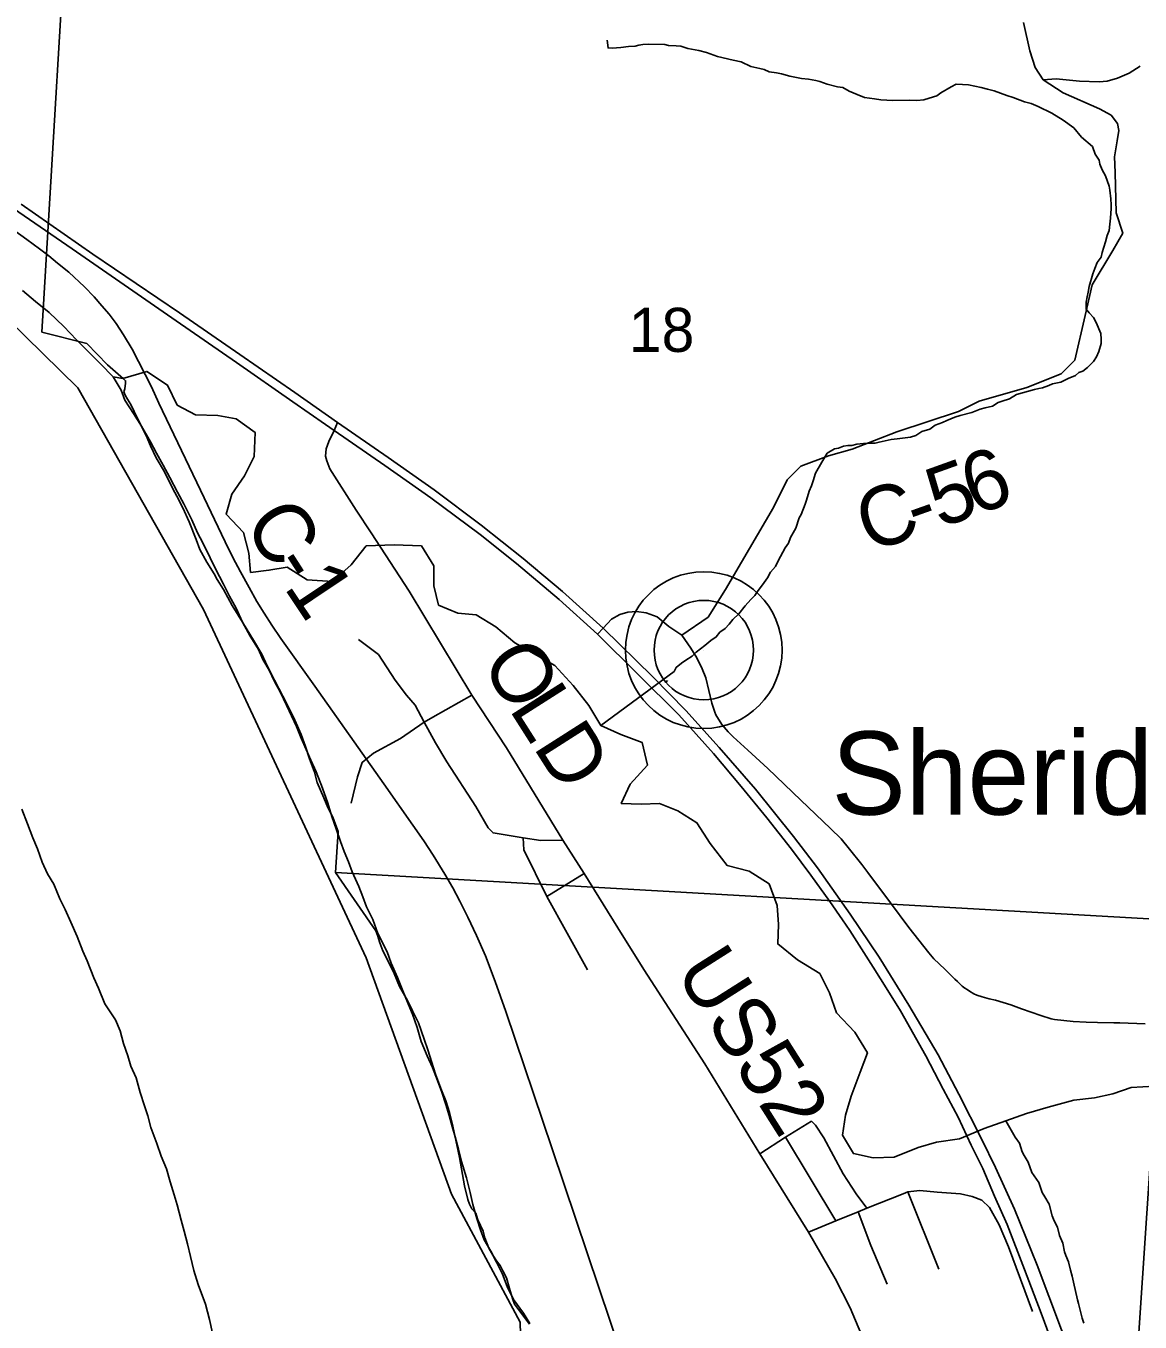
# Model space of a CAD drawing. Extents: x 0 to 45.4, y -2.2 to 22.
# Drawn here: x 2.837 to 3.896, y 17.917 to 19.147 of the extents above; entities that cross this region are included whole.
import ezdxf

# ---------------------------------------------------------------- set-up
doc = ezdxf.new("R2010")
doc.units = 0
for name, color, linetype in [('GM_X_Corporation', 7, 'Continuous'), ('GM_X_County_Road', 7, 'Continuous'), ('GM_X_County_Road_Text', 7, 'Continuous'), ('GM_X_Major_River', 7, 'Continuous'), ('GM_X_Minor_River', 7, 'Continuous'), ('GM_X_Rail_Line', 7, 'Continuous'), ('GM_X_Section_Text', 7, 'Continuous'), ('GM_X_Township_Road', 7, 'Continuous'), ('GM_X_Unincorporated', 7, 'Continuous'), ('GM_X_Unincorporated_Location', 7, 'Continuous'), ('GM_X_Unincorporated_Text', 7, 'Continuous'), ('GM_X_US_Route', 7, 'Continuous')]:
    doc.layers.add(name, color=color, linetype=linetype)

msp = doc.modelspace()

# ---------------------------------------------------------------- linework, layer by layer
at = {"layer": 'GM_X_Corporation'}
for points in [[(3.9206, 18.2985), (3.1315, 18.3434), (3.1341, 18.3824), (3.1315, 18.3892), (3.1288, 18.3961), (3.1243, 18.4052), (3.1205, 18.4143), (3.1141, 18.429), (3.1114, 18.4389), (3.1069, 18.4514), (3.1031, 18.4631), (3.099, 18.4745), (3.0929, 18.4882), (3.0857, 18.5029), (3.0736, 18.5261), (3.0649, 18.5431), (3.0615, 18.5507), (3.0536, 18.5639), (3.043, 18.581), (3.0335, 18.5969), (3.0252, 18.6121), (3.0191, 18.6216), (3.0161, 18.6269), (3.0093, 18.6382), (3.0025, 18.65), (2.9991, 18.6595), (2.9926, 18.6765), (2.9866, 18.6898), (2.9809, 18.7008), (2.9771, 18.7076), (2.9692, 18.7239), (2.9612, 18.7372), (2.9559, 18.7485), (2.9518, 18.7584), (2.9438, 18.7739), (2.937, 18.7879), (2.934, 18.7929), (2.9317, 18.7967), (2.9306, 18.7997), (2.9313, 18.8027), (2.9321, 18.808), (2.9321, 18.8103), (2.9302, 18.8122), (2.9151, 18.8255), (2.8954, 18.8456), (2.8526, 18.8566), (2.8813, 19.3385)], [(2.4503, 19.1527), (2.5862, 19.0536), (2.6706, 19.0104), (2.7255, 18.9508), (2.8035, 18.8848), (2.8867, 18.8036), (3.006, 18.5933), (3.1607, 18.2624), (3.2417, 18.0381), (3.3068, 17.9167), (3.3076, 17.8928), (3.2906, 17.8503), (3.2853, 17.7584), (3.3008, 17.64), (3.3557, 17.2765), (3.3572, 17.2298), (3.3712, 17.1086)], [(2.4503, 19.1527), (2.5862, 19.0536), (2.6706, 19.0104), (2.7255, 18.9508), (2.8035, 18.8848), (2.8867, 18.8036), (3.006, 18.5933), (3.1607, 18.2624), (3.2417, 18.0381), (3.3068, 17.9167), (3.3076, 17.8928), (3.2906, 17.8503), (3.2853, 17.7584), (3.3008, 17.64), (3.3557, 17.2765), (3.3572, 17.2298), (3.3712, 17.1086)], [(3.3157, 17.9148), (3.3104, 17.922), (3.3051, 17.9288), (3.3013, 17.9337), (3.2994, 17.939), (3.2968, 17.9485), (3.2937, 17.9587), (3.2903, 17.9655), (3.2877, 17.9705), (3.2843, 17.975), (3.2809, 17.9803), (3.2771, 17.9868), (3.2733, 17.9966), (3.2718, 18.0031), (3.2665, 18.0137), (3.2646, 18.0201), (3.2608, 18.0243), (3.2586, 18.0288), (3.257, 18.033), (3.254, 18.0459), (3.2521, 18.0569), (3.2491, 18.0728), (3.2457, 18.0895), (3.2423, 18.1054), (3.2397, 18.1156), (3.2363, 18.1266), (3.2321, 18.1368), (3.2264, 18.152), (3.2192, 18.1751), (3.2158, 18.1853), (3.2102, 18.2009), (3.2045, 18.2123), (3.1999, 18.2221), (3.1924, 18.2354), (3.1871, 18.2475), (3.1814, 18.2593), (3.1765, 18.2691), (3.1735, 18.2767), (3.1712, 18.2839), (3.1697, 18.2881), (3.1315, 18.3434), (3.9206, 18.2985), (3.854, 17.3067)]]:
    msp.add_lwpolyline(points, dxfattribs=at)
msp.add_lwpolyline([(3.9206, 18.2985), (5.0121, 18.2353), (4.9524, 17.2347), (3.854, 17.3067)], close=True, dxfattribs=at)
at = {"layer": 'GM_X_County_Road'}
for points in [[(3.4602, 18.5689), (3.4852, 18.5858), (3.5019, 18.6121), (3.5474, 18.6901), (3.5604, 18.7162), (3.5734, 18.7292), (3.5995, 18.7389), (3.6222, 18.7454), (3.6645, 18.7617), (3.7231, 18.7812), (3.7426, 18.7909), (3.7881, 18.8039), (3.8207, 18.8169), (3.8337, 18.8299), (3.8434, 18.8722), (3.8499, 18.9015), (3.8695, 18.934), (3.8792, 18.9503), (3.8727, 18.9698), (3.8718, 19.0081), (3.8711, 19.0228), (3.8737, 19.0382), (3.8752, 19.048), (3.874, 19.0546), (3.868, 19.0624), (3.857, 19.0684), (3.8224, 19.0835), (3.8036, 19.0961), (3.796, 19.1077), (3.7907, 19.1234), (3.7847, 19.1505)], [(3.1333, 18.7707), (3.1302, 18.763), (3.125, 18.7526), (3.1225, 18.7457), (3.122, 18.7386), (3.1233, 18.7342), (3.1262, 18.7268), (3.1512, 18.6874), (3.1652, 18.6661)], [(3.1652, 18.6661), (3.2013, 18.6106), (3.261, 18.5117), (3.2937, 18.4617), (3.3474, 18.3741), (3.3677, 18.3426), (3.3996, 18.2909), (3.4243, 18.2515), (3.4822, 18.1618), (3.5344, 18.0765), (3.5806, 18.002), (3.606, 17.9581), (3.6201, 17.9303), (3.6499, 17.8596)], [(3.3803, 18.5697), (3.3857, 18.5755), (3.3936, 18.5841), (3.4014, 18.5885), (3.409, 18.5907), (3.4173, 18.5914), (3.4266, 18.5899), (3.4369, 18.5863), (3.448, 18.5769), (3.4602, 18.5689), (3.4688, 18.5566), (3.4745, 18.5473), (3.4796, 18.5367), (3.483, 18.5284), (3.4888, 18.5044), (3.4916, 18.4956), (3.4926, 18.4931), (3.4983, 18.4841), (3.4987, 18.4836), (3.5042, 18.4769), (3.5091, 18.4722), (3.523, 18.4596), (3.542, 18.4421), (3.5735, 18.4121), (3.6016, 18.3853), (3.6115, 18.3754), (3.6197, 18.3655), (3.6312, 18.3511), (3.6371, 18.3436), (3.6584, 18.3146), (3.6759, 18.2913), (3.6949, 18.2672), (3.6997, 18.2617), (3.71, 18.2517), (3.7189, 18.2429), (3.7197, 18.2422), (3.722, 18.2399), (3.7267, 18.2357), (3.7291, 18.2337), (3.7314, 18.2323), (3.7335, 18.2309), (3.7375, 18.2284), (3.7406, 18.2271), (3.7457, 18.2254), (3.7521, 18.2237), (3.7583, 18.2222), (3.7729, 18.2179), (3.7829, 18.2142), (3.8013, 18.2079), (3.8112, 18.2047), (3.8142, 18.2041), (3.8232, 18.2029), (3.8319, 18.202), (3.8444, 18.2014), (3.8552, 18.2012), (3.8707, 18.2007), (3.8764, 18.2008), (3.9002, 18.1998)]]:
    msp.add_lwpolyline(points, dxfattribs=at)
at = {"layer": 'GM_X_Major_River'}
for points in [[(3.1438, 18.3535), (3.1396, 18.3633), (3.1362, 18.3728), (3.132, 18.3849), (3.1279, 18.3967), (3.1241, 18.4092), (3.1192, 18.4236), (3.1132, 18.4392), (3.1082, 18.4502), (3.1037, 18.4604), (3.0988, 18.4711), (3.0943, 18.4821), (3.0897, 18.4923), (3.0848, 18.5025), (3.0788, 18.5151), (3.0735, 18.5249), (3.0686, 18.5355), (3.0625, 18.5458), (3.0584, 18.5553), (3.0504, 18.5678), (3.0432, 18.5811), (3.0372, 18.5943), (3.0308, 18.6057), (3.0251, 18.6171), (3.0175, 18.6319), (3.0123, 18.6421), (3.0054, 18.6566), (3.0005, 18.666), (2.9949, 18.6782), (2.9873, 18.6934), (2.9813, 18.7047), (2.9741, 18.7184), (2.9677, 18.7302), (2.9616, 18.7415), (2.9559, 18.7522), (2.9472, 18.7673), (2.9397, 18.7791), (2.9314, 18.792), (2.928, 18.8015), (2.9204, 18.814), (2.9083, 18.8265), (2.8955, 18.839), (2.8856, 18.8493), (2.8735, 18.8618), (2.8595, 18.8751), (2.8467, 18.8857), (2.8342, 18.8959)], [(2.8337, 18.4036), (2.839, 18.3896), (2.8439, 18.3763), (2.8484, 18.3661), (2.853, 18.3532), (2.8579, 18.3422), (2.8639, 18.3323), (2.8696, 18.3186), (2.8749, 18.3084), (2.8802, 18.2963), (2.8862, 18.2826), (2.8915, 18.2689), (2.8957, 18.2595), (2.9021, 18.2435), (2.9063, 18.2337), (2.9123, 18.2189), (2.9225, 18.2037), (2.927, 18.1931), (2.9301, 18.1813), (2.9342, 18.1696), (2.9372, 18.1597), (2.9422, 18.1487), (2.9459, 18.1346), (2.9501, 18.1221), (2.9531, 18.1126), (2.9561, 18.1013), (2.9618, 18.0861), (2.966, 18.0743), (2.9709, 18.0622), (2.9746, 18.05), (2.9784, 18.0375), (2.9811, 18.028), (2.9849, 18.0136), (2.9879, 18.003), (2.9909, 17.9909), (2.9939, 17.9791), (2.9969, 17.9658)], [(3.3161, 17.9153), (3.31, 17.9251), (3.3006, 17.938), (3.2945, 17.9506), (3.29, 17.9623), (3.2843, 17.9737), (3.279, 17.9839), (3.2726, 17.9949), (3.2692, 18.0044), (3.2658, 18.0151), (3.262, 18.0283), (3.2594, 18.0397), (3.256, 18.0538), (3.2511, 18.0693), (3.2484, 18.0807), (3.245, 18.0925), (3.2424, 18.1023), (3.2394, 18.1129), (3.2363, 18.1232), (3.2326, 18.1349), (3.2284, 18.1459), (3.2235, 18.1585), (3.2186, 18.1695), (3.2129, 18.1831), (3.2091, 18.1964), (3.2046, 18.2089), (3.2004, 18.2188), (3.1948, 18.2328), (3.1902, 18.2438), (3.1842, 18.2575), (3.1804, 18.2681), (3.1717, 18.2856), (3.1668, 18.2988), (3.1608, 18.311), (3.1574, 18.3205), (3.1536, 18.3303), (3.1472, 18.344), (3.1438, 18.3535)], [(2.9969, 17.9658), (3.0011, 17.9525), (3.0079, 17.9336), (3.0117, 17.9192), (3.0147, 17.9063)]]:
    msp.add_lwpolyline(points, dxfattribs=at)
at = {"layer": 'GM_X_Minor_River'}
for points in [[(3.8443, 18.8782), (3.8444, 18.885), (3.8452, 18.89), (3.8461, 18.8945), (3.8473, 18.8998), (3.8505, 18.9119), (3.8525, 18.9168), (3.8549, 18.9225), (3.8584, 18.9277), (3.8596, 18.9322), (3.8628, 18.9421), (3.8644, 18.9481), (3.866, 18.953), (3.8669, 18.9591), (3.8674, 18.9648), (3.8679, 18.9739), (3.868, 18.9773), (3.8677, 18.983), (3.8667, 18.9914), (3.866, 18.9952), (3.8628, 19.0047), (3.8595, 19.0105), (3.8573, 19.0158), (3.8566, 19.0196), (3.8529, 19.0254), (3.8504, 19.0326), (3.8399, 19.0416), (3.8325, 19.0504), (3.8224, 19.0578), (3.8116, 19.0644), (3.7988, 19.0707), (3.792, 19.0735), (3.7856, 19.0751), (3.7751, 19.0791), (3.769, 19.0811), (3.757, 19.0855), (3.7506, 19.0871), (3.7446, 19.0887), (3.7325, 19.0912), (3.7268, 19.0917), (3.7208, 19.0918), (3.7162, 19.0892), (3.7062, 19.0837), (3.7024, 19.0807), (3.6951, 19.0786), (3.6902, 19.0771), (3.6834, 19.0765), (3.6769, 19.0766), (3.6606, 19.0765), (3.6493, 19.0771), (3.6432, 19.0779), (3.6338, 19.0792), (3.627, 19.082), (3.6191, 19.0852), (3.6131, 19.0887), (3.6082, 19.0895), (3.5984, 19.092), (3.5913, 19.0944), (3.5875, 19.0952), (3.5807, 19.0965), (3.5739, 19.0973), (3.5629, 19.0994), (3.555, 19.1018), (3.5501, 19.1027), (3.5433, 19.1036), (3.5384, 19.1059), (3.5343, 19.1068), (3.526, 19.1088), (3.5166, 19.1131), (3.509, 19.1148), (3.4943, 19.1181), (3.4838, 19.122), (3.4766, 19.1237), (3.4661, 19.1258), (3.4593, 19.1278), (3.4551, 19.1282), (3.4476, 19.1287), (3.4442, 19.1295), (3.4286, 19.1298), (3.4233, 19.1295), (3.4195, 19.1288), (3.4161, 19.1281), (3.4097, 19.1275), (3.4024, 19.1268), (3.3941, 19.1262), (3.3903, 19.1263), (3.3893, 19.1335)], [(3.3835, 18.4829), (3.453, 18.5344), (3.4549, 18.5382), (3.4599, 18.5423), (3.4642, 18.5452), (3.4703, 18.5489), (3.4741, 18.5526), (3.4822, 18.559), (3.488, 18.5638), (3.493, 18.5671), (3.4964, 18.5716), (3.5014, 18.575), (3.5053, 18.5791), (3.5088, 18.5836), (3.5146, 18.5892), (3.5204, 18.5967), (3.5258, 18.6026), (3.5296, 18.6064), (3.5327, 18.6113), (3.5359, 18.6154), (3.5386, 18.6188), (3.5417, 18.6233), (3.5444, 18.6285), (3.5494, 18.6341), (3.5518, 18.6394), (3.5585, 18.6518), (3.5616, 18.656), (3.5636, 18.6616), (3.5686, 18.6703), (3.5718, 18.6801), (3.5738, 18.6835), (3.5774, 18.6933), (3.5786, 18.6971), (3.5814, 18.7054), (3.5834, 18.7106), (3.585, 18.7152), (3.5874, 18.7227), (3.5932, 18.7329), (3.5983, 18.7415), (3.6052, 18.7456), (3.609, 18.7463), (3.6139, 18.7481), (3.6181, 18.7488), (3.6219, 18.7487), (3.6265, 18.7502), (3.6329, 18.7508), (3.6382, 18.7511), (3.6439, 18.751), (3.6477, 18.7521), (3.6591, 18.7545), (3.6648, 18.7552), (3.6698, 18.7559), (3.6774, 18.7569), (3.6827, 18.7583), (3.6884, 18.762), (3.6957, 18.7645), (3.701, 18.7683), (3.7079, 18.7708), (3.7121, 18.7726), (3.7197, 18.7759), (3.7247, 18.7773), (3.7357, 18.7802), (3.7437, 18.7835), (3.7483, 18.7845), (3.7555, 18.7863), (3.7609, 18.7896), (3.7647, 18.7911), (3.7715, 18.7933), (3.7781, 18.7973), (3.7838, 18.7987), (3.7952, 18.802), (3.7994, 18.803), (3.8028, 18.8037), (3.8089, 18.8059), (3.8123, 18.8074), (3.8203, 18.8091), (3.8272, 18.8124), (3.8341, 18.8154), (3.8375, 18.818), (3.8413, 18.8194), (3.8455, 18.8228), (3.8513, 18.8287), (3.8541, 18.8329), (3.8564, 18.8381), (3.8585, 18.8457), (3.8585, 18.8499), (3.8582, 18.8552), (3.8539, 18.8655), (3.8513, 18.8705), (3.8472, 18.8747), (3.8443, 18.8782)], [(2.9204, 18.814), (2.9296, 18.8125), (2.9524, 18.8192), (2.972, 18.8062), (2.981, 18.7872), (2.9984, 18.7781), (3.0196, 18.7772), (3.037, 18.7741), (3.0551, 18.7612), (3.0543, 18.7384), (3.0451, 18.7202), (3.0329, 18.7028), (3.0275, 18.6838), (3.0441, 18.6663), (3.0493, 18.6465), (3.0508, 18.6283), (3.0682, 18.6305), (3.0856, 18.6335), (3.1045, 18.6213), (3.1287, 18.6197), (3.1462, 18.6356), (3.1607, 18.6537), (3.1872, 18.6544), (3.213, 18.6535), (3.225, 18.6345), (3.2249, 18.6155), (3.2294, 18.5973), (3.2475, 18.5896), (3.2649, 18.5881), (3.2838, 18.5766), (3.3019, 18.5614), (3.3223, 18.5499), (3.3397, 18.54), (3.3571, 18.5209), (3.3721, 18.5019), (3.3834, 18.4829), (3.4023, 18.4744), (3.4227, 18.4668), (3.4279, 18.4455), (3.4112, 18.4273), (3.4028, 18.4091), (3.4217, 18.4083), (3.4391, 18.409), (3.4565, 18.4021), (3.4747, 18.3907), (3.4874, 18.3709), (3.5033, 18.3503), (3.5244, 18.3449), (3.5433, 18.3327), (3.5508, 18.3122), (3.5523, 18.294), (3.5514, 18.2757), (3.5703, 18.2605), (3.5914, 18.2475), (3.6005, 18.2292), (3.6072, 18.2102), (3.6245, 18.192), (3.6366, 18.1722), (3.6297, 18.154), (3.6213, 18.1312), (3.6159, 18.113), (3.6128, 18.0941), (3.6233, 18.0766), (3.6422, 18.0727), (3.6619, 18.0734), (3.6847, 18.0824), (3.7021, 18.0876), (3.7241, 18.0906), (3.7476, 18.1004), (3.7681, 18.1079), (3.7878, 18.1147), (3.8083, 18.1207), (3.8325, 18.1274), (3.8522, 18.1296), (3.8697, 18.1333), (3.8871, 18.1393), (3.9091, 18.1408)], [(3.4447, 18.5235), (3.4468, 18.5258)], [(3.7681, 18.1079), (3.777, 18.0922), (3.7811, 18.0864), (3.7836, 18.0784), (3.7854, 18.0749), (3.7891, 18.0684), (3.7927, 18.0588), (3.7994, 18.0492), (3.8026, 18.0397), (3.8052, 18.0355), (3.8092, 18.0286), (3.812, 18.0175), (3.8139, 18.0129), (3.8172, 18.0068), (3.8189, 17.9988), (3.8222, 17.9915), (3.8236, 17.9835), (3.825, 17.98), (3.8276, 17.9739), (3.8293, 17.9659), (3.8311, 17.9602), (3.8322, 17.9545), (3.836, 17.9377), (3.8371, 17.9343), (3.8406, 17.9205), (3.8421, 17.9156)]]:
    msp.add_lwpolyline(points, dxfattribs=at)
at = {"layer": 'GM_X_Rail_Line'}
msp.add_lwpolyline([(3.4019, 17.8893), (3.3818, 17.9486), (3.3372, 18.0811), (3.2931, 18.2115), (3.2832, 18.2399), (3.2738, 18.2643), (3.2654, 18.2838), (3.2572, 18.3012), (3.2496, 18.3163), (3.2428, 18.329), (3.2354, 18.3419), (3.2242, 18.3598), (3.2155, 18.3735), (3.205, 18.3885), (3.1773, 18.4278), (3.1117, 18.5203), (3.0797, 18.5656), (3.0711, 18.5784), (3.0638, 18.5898), (3.0568, 18.6008), (3.0494, 18.6141), (3.0411, 18.6288), (3.0341, 18.6425), (3.0267, 18.6575), (3.0033, 18.7065), (2.9638, 18.789), (2.9566, 18.8045), (2.9384, 18.8403), (2.93, 18.8538), (2.9231, 18.8646), (2.9164, 18.8734), (2.9097, 18.8816), (2.9024, 18.8899), (2.893, 18.8994), (2.8781, 18.9133), (2.8676, 18.9218), (2.8592, 18.9288), (2.8505, 18.9354), (2.8383, 18.9445), (2.7294, 19.0226)], dxfattribs=at)
at = {"layer": 'GM_X_Township_Road'}
for p, q in [((3.261, 18.5117), (3.2238, 18.4909)), ((3.3321, 18.3208), (3.3677, 18.3426)), ((3.5587, 18.0921), (3.6066, 18.0129)), ((3.675, 18.0403), (3.7044, 17.9669))]:
    msp.add_line(p, q, dxfattribs=at)
for points in [[(3.8036, 19.0961), (3.8158, 19.097), (3.8381, 19.0948), (3.8567, 19.0942), (3.8642, 19.0948), (3.874, 19.0977), (3.885, 19.1024), (3.8957, 19.109)], [(3.1532, 18.5648), (3.1724, 18.5503), (3.188, 18.5261), (3.199, 18.5117), (3.207, 18.5022), (3.2156, 18.4863), (3.2263, 18.4666), (3.2373, 18.4487), (3.2646, 18.406), (3.2766, 18.3859), (3.2811, 18.3811), (3.3098, 18.3765), (3.3265, 18.3738), (3.3474, 18.3741)], [(3.2238, 18.4909), (3.2156, 18.4863), (3.1931, 18.4707), (3.1676, 18.4569), (3.1569, 18.448), (3.1525, 18.4343), (3.1462, 18.4092)], [(3.3098, 18.3765), (3.3103, 18.3649), (3.3321, 18.3208), (3.3707, 18.2511)], [(3.5344, 18.0765), (3.5587, 18.0921), (3.5834, 18.1075)], [(3.5834, 18.1075), (3.5873, 18.1037), (3.5952, 18.0917), (3.6136, 18.0575), (3.6259, 18.0384), (3.6361, 18.025)], [(3.5806, 18.002), (3.6066, 18.0129), (3.6278, 18.0215), (3.6361, 18.025), (3.6704, 18.0384), (3.675, 18.0403), (3.6863, 18.0415), (3.7028, 18.04), (3.725, 18.0383), (3.7362, 18.0359)], [(3.7362, 18.0359), (3.7452, 18.0324), (3.7525, 18.0254), (3.7616, 18.009), (3.7707, 17.988), (3.7933, 17.9269)], [(3.6278, 18.0215), (3.6397, 17.9895), (3.6553, 17.9526)]]:
    msp.add_lwpolyline(points, dxfattribs=at)
at = {"layer": 'GM_X_Unincorporated'}
for radius in [0.0744, 0.0472]:
    msp.add_circle((3.4812, 18.5546), radius, dxfattribs=at)
at = {"layer": 'GM_X_Unincorporated_Location'}
msp.add_line((3.4812, 18.5546), (3.4812, 18.5546), dxfattribs=at)
at = {"layer": 'GM_X_US_Route'}
for points in [[(2.1, 19.4307), (2.1525, 19.408), (2.2048, 19.3847), (2.2481, 19.3663), (2.2904, 19.3467), (2.3168, 19.3334), (2.3481, 19.3149), (2.3733, 19.2978), (2.3971, 19.2806), (2.428, 19.2587), (2.4703, 19.2279), (2.5147, 19.1965), (2.5575, 19.1656), (2.5988, 19.1361), (2.6483, 19.1006), (2.6861, 19.0735), (2.7238, 19.0463), (2.7549, 19.0241), (2.8309, 18.9705), (2.8814, 18.9354), (2.9802, 18.8671), (3.0375, 18.8275), (3.0908, 18.7902), (3.122, 18.7687)], [(2.8331, 18.978), (2.9009, 18.9306), (2.9833, 18.8748), (3.0406, 18.8352), (3.0929, 18.7993), (3.1333, 18.7707), (3.1815, 18.7374), (3.2251, 18.7068), (3.2697, 18.6732), (3.3097, 18.6416), (3.347, 18.6103), (3.3857, 18.5755), (3.4329, 18.5291), (3.4641, 18.4973), (3.4958, 18.4622), (3.5303, 18.4227), (3.5663, 18.3776), (3.5892, 18.348), (3.6202, 18.3038), (3.6476, 18.263), (3.676, 18.2175), (3.7037, 18.1705), (3.7235, 18.1332), (3.7452, 18.0901), (3.7583, 18.0635), (3.7761, 18.024), (3.7977, 17.9707), (3.832, 17.8799)], [(3.122, 18.7687), (3.1302, 18.763), (3.1784, 18.7298), (3.222, 18.6992), (3.2689, 18.6643), (3.3033, 18.6368), (3.3439, 18.6026), (3.3803, 18.5697), (3.4574, 18.4931), (3.4905, 18.4565), (3.5168, 18.4251), (3.5411, 18.3955), (3.5645, 18.3657), (3.5829, 18.3409), (3.6009, 18.3161), (3.6129, 18.2985)], [(3.6129, 18.2985), (3.6198, 18.2884), (3.642, 18.2535), (3.6559, 18.2316)], [(3.6559, 18.2316), (3.6681, 18.2121), (3.692, 18.1695), (3.7086, 18.1377), (3.7227, 18.1111), (3.7352, 18.0846), (3.7461, 18.0624), (3.7573, 18.0361), (3.7693, 18.0094), (3.7859, 17.9667), (3.8017, 17.9252), (3.8218, 17.8703), (3.844, 17.8104), (3.8705, 17.741), (3.8889, 17.6918), (3.9068, 17.6433), (3.9256, 17.5933), (3.9474, 17.535), (3.965, 17.4877), (3.9833, 17.4403), (4.0032, 17.3873)]]:
    msp.add_lwpolyline(points, dxfattribs=at)

# ---------------------------------------------------------------- texts
at = {"layer": 'GM_X_County_Road_Text'}
for s, height, rotation, p in [('6', 0.0568, 19.8238, (3.7384, 18.682)), ('5', 0.0568, 19.7675, (3.7054, 18.6701)), ('C', 0.0568, 18.2134, (3.6375, 18.6471)), ('C', 0.0568, 302.372, (3.0433, 18.6748)), ('-', 0.0568, 19.6378, (3.6833, 18.6622)), ('-', 0.0568, 302.7063, (3.0684, 18.6351)), ('1', 0.0568, 303.7976, (3.0817, 18.6145)), ('O', 0.0568, 301.0729, (3.2689, 18.5431)), ('L', 0.0568, 302.4533, (3.2955, 18.499)), ('D', 0.0568, 302.5044, (3.3184, 18.4631)), ('US52', 0.05682, 302.3564, (3.453, 18.2497))]:
    msp.add_text(s, height=height, rotation=rotation, dxfattribs=at).set_placement(p)
at = {"layer": 'GM_X_Section_Text'}
msp.add_text('18', height=0.04186, rotation=0, dxfattribs=at).set_placement((3.41, 18.8377))
at = {"layer": 'GM_X_Unincorporated_Text'}
msp.add_text('Sheridan', height=0.07898, rotation=0, dxfattribs=at).set_placement((3.6025, 18.3984))

doc.saveas('drawing.dxf')
